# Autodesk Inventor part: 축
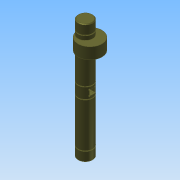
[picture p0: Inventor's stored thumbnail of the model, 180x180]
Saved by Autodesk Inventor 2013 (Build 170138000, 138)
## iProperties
Company: 한국ATC센터
Created: 2015-04
Part Number: 축
Document SubType Name: Modeling
Designer: KYOUNG IL JANG
Density: 7.85 g/cm^3
Material: 강
Mass: 606.905 g
Surface Area: 163.755 cm^2
Volume: 77.3127 cm^3
Author: KYOUNG IL JANG
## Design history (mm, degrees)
sketch "스케치1"
  geometry: C1 r 11 at (0, 0); 1 further point
  constraints: 1 centre point, 1 coincident
  dimensions: "d0" = 22 diameter of C1
extrude "돌출1" new body sketch "스케치1" stored distance "d1" = 180; taper "d2" = 0 deg
sketch "스케치2"
  geometry: L1 (-10.247, -4)-(10.247, -4); L2 (-10.247, 4)-(10.247, 4); A1 r 11 centre (0, 0) between (-10.247, -4) and (10.247, -4) reference; 1 further point
  constraints: 4 end point, 4 point on circle, 2 parallel, 1 horizontal
  dimensions: "d3" = 8 distance between parallel lines of L2 L1
extrude "돌출2" cut sketch "스케치2" stored distance "d4" = 8; taper "d5" = 0 deg
sketch "스케치3"
  geometry: 5 further points
hole "구멍1" sketch "스케치3" at (-4, 4), (4, 4), (4, -4), (-4, -4) diameter "d6" = 2; stored, may be unused: countersink angle "d10" = 90 deg, drill point angle "d12" = 118 deg; dims "d7" = 6, "d8" = 4, "d9" = 2, "d11" = 8
chamfer "모따기1" distance "d13" = 1; stored, may be unused: second distance "d14" = 2, angle "d15" = 45 deg
sketch "스케치4"
  geometry: L1 (-10, 9)-(-11, 9); L2 (-11, 9)-(-11, 7.8); L3 (-11, 7.8)-(-10, 7.8); L4 (-10, 7.8)-(-10, 9); L5 (-10, 90)-(10, 90) reference; L6 (0, -15)-(0, 90) reference; L7 (-10, 74.8)-(-11, 74.8); L8 (-11, 74.8)-(-11, 76); L9 (-11, 76)-(-10, 76); L10 (-10, 76)-(-10, 74.8); 1 further point
  constraints: 16 end point, 4 parallel, 2 equal length, 2 horizontal, 2 perpendicular, 1 collinear
  dimensions: "d16" = 7.8 distance from line of L3 point (0, 0); "d17" = 82.2 distance between parallel lines of L3 L5 (derived); "d18" = 11 distance from line of point (0, 0) L2; "d19" = 1 distance of L2.end L3.end; "d20" = 1.2 distance of L1.end L2.end; "d27" = 14 distance between parallel lines of L5 L9
revolve "회전1" sketch "스케치4" stored, may be unused: angle "d21" = 90 deg
sketch "스케치5"
  geometry: L1 (11, 52)-(-7, 52); L2 (-7, 52)-(-7, 69); L3 (-7, 69)-(11, 69); L4 (11, 69)-(11, 52); 1 further point
  constraints: 8 end point, 2 parallel, 1 horizontal, 1 perpendicular
  dimensions: "d22" = 17 distance of L3.end L1.start; "d23" = 36 diameter of L4 L2; "d24" = 7 horizontal distance of L2.end point (0, 0); "d25" = 52 distance from line of L1 point (0, 0)
revolve "회전2" sketch "스케치5" stored, may be unused: angle "d26" = 90 deg
node "솔리드1"
mirror "대칭1"
mirror "대칭2"
